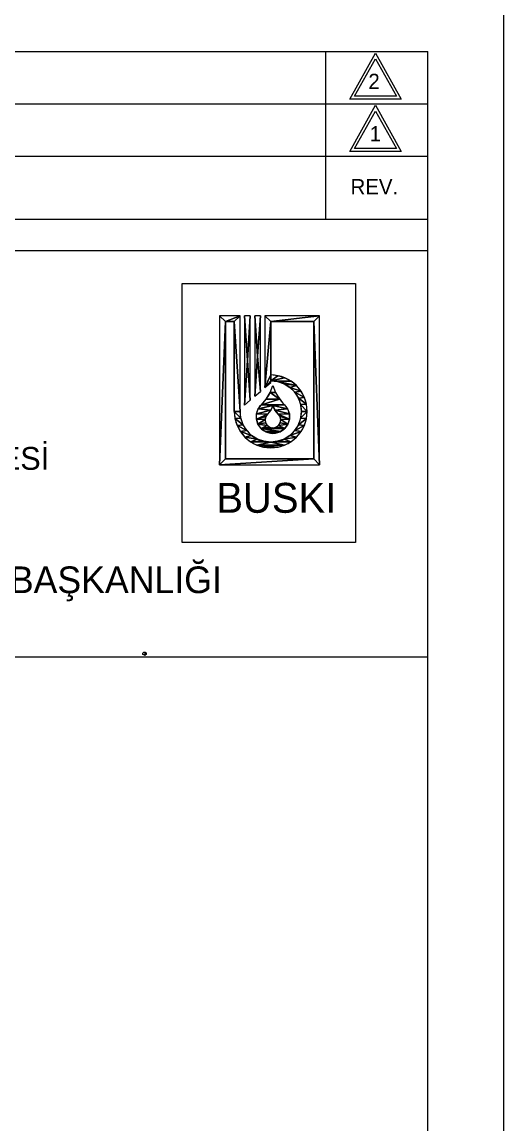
# Model space of a CAD drawing. Extents: x -10 to 1145, y -10 to 821.
# Drawn here: x 1081.7 to 1145, y 138.4 to 283.1 of the extents above; entities that cross this region are included whole.
import ezdxf

# ---------------------------------------------------------------- set-up
doc = ezdxf.new("R2010")
doc.units = 0
for name, color, linetype in [('Level 1', 7, 'Continuous'), ('Level 20', 7, 'Continuous'), ('Level 21', 7, 'Continuous'), ('Level 51', 7, 'Continuous'), ('Level 6', 7, 'Continuous'), ('Level 7', 7, 'Continuous'), ('Level 8', 7, 'Continuous')]:
    doc.layers.add(name, color=color, linetype=linetype)

msp = doc.modelspace()

# ---------------------------------------------------------------- linework, layer by layer
at = {"layer": 'Level 1'}
msp.add_lwpolyline([(1097.86, 200.4), (1097.9, 200.4), (1097.99, 200.36), (1098.03, 200.27), (1098.03, 200.1), (1097.94, 200.02), (1097.82, 199.97), (1097.69, 200.02), (1097.6, 200.1), (1097.6, 200.27), (1097.65, 200.36), (1097.73, 200.4), (1097.86, 200.4), (1097.99, 200.27), (1097.99, 200.14), (1097.9, 200.06), (1097.82, 199.97), (1097.9, 200.1), (1097.9, 200.31), (1097.86, 200.4)], dxfattribs=at)
msp.add_lwpolyline([(1097.86, 200.4), (1097.9, 200.4), (1097.99, 200.36), (1098.03, 200.27), (1098.03, 200.1), (1097.94, 200.02), (1097.82, 199.97), (1097.69, 200.02), (1097.6, 200.1), (1097.6, 200.27), (1097.65, 200.36), (1097.73, 200.4), (1097.86, 200.4), (1097.99, 200.27), (1097.99, 200.14), (1097.9, 200.06), (1097.82, 199.97), (1097.9, 200.1), (1097.9, 200.31), (1097.86, 200.4)], dxfattribs=at)
msp.add_lwpolyline([(1097.86, 200.4), (1097.9, 200.4), (1097.99, 200.36), (1098.03, 200.27), (1098.03, 200.1), (1097.94, 200.02), (1097.82, 199.97), (1097.69, 200.02), (1097.6, 200.1), (1097.6, 200.27), (1097.65, 200.36), (1097.73, 200.4), (1097.86, 200.4), (1097.99, 200.27), (1097.99, 200.14), (1097.9, 200.06), (1097.82, 199.97), (1097.9, 200.1), (1097.9, 200.31), (1097.86, 200.4)], dxfattribs=at)
msp.add_lwpolyline([(1097.86, 200.4), (1097.9, 200.4), (1097.99, 200.36), (1098.03, 200.27), (1098.03, 200.1), (1097.94, 200.02), (1097.82, 199.97), (1097.69, 200.02), (1097.6, 200.1), (1097.6, 200.27), (1097.65, 200.36), (1097.73, 200.4), (1097.86, 200.4), (1097.99, 200.27), (1097.99, 200.14), (1097.9, 200.06), (1097.82, 199.97), (1097.9, 200.1), (1097.9, 200.31), (1097.86, 200.4)], dxfattribs=at)
at = {"layer": 'Level 51'}
msp.add_lwpolyline([(-10, -10), (1145, -10), (1145, 821), (-10, 821)], close=True, dxfattribs=at)
at = {"layer": 'Level 6'}
for p, q in [((967.03, 279.24), (1135, 279.24)), ((967.03, 279.24), (1135, 279.24)), ((967.03, 279.24), (1135, 279.24)), ((967.03, 279.24), (1135, 279.24)), ((970.15, 279.24), (1131.87, 279.24)), ((970.15, 279.24), (1131.87, 279.24)), ((970.15, 279.24), (1131.87, 279.24)), ((970.15, 279.24), (1131.87, 279.24)), ((970.15, 279.24), (1131.87, 279.24)), ((970.15, 279.24), (1131.87, 279.24)), ((970.15, 279.24), (1131.87, 279.24)), ((970.15, 279.24), (1131.87, 279.24)), ((1121.62, 257.23), (1121.62, 279.24)), ((1121.62, 257.23), (1121.62, 279.24)), ((1121.62, 257.23), (1121.62, 279.24)), ((1121.62, 257.23), (1121.62, 279.24)), ((1135, 255.72), (1135, 279.24)), ((1135, 255.72), (1135, 279.24)), ((1135, 255.72), (1135, 279.24)), ((1135, 255.72), (1135, 279.24)), ((1135, 255.72), (1135, 279.24)), ((1135, 255.72), (1135, 279.24)), ((1135, 255.72), (1135, 279.24)), ((1135, 255.72), (1135, 279.24)), ((967.03, 272.38), (1135, 272.38)), ((967.03, 272.38), (1135, 272.38)), ((967.03, 272.38), (1135, 272.38)), ((967.03, 272.38), (1135, 272.38)), ((967.03, 265.52), (1135, 265.52)), ((967.03, 265.52), (1135, 265.52)), ((967.03, 265.52), (1135, 265.52)), ((967.03, 265.52), (1135, 265.52)), ((1135, 0), (1135, 262.93)), ((1135, 0), (1135, 262.93)), ((1135, 0), (1135, 262.93)), ((1135, 0), (1135, 262.93)), ((967.03, 257.23), (1135, 257.23)), ((967.03, 257.23), (1135, 257.23)), ((967.03, 257.23), (1135, 257.23)), ((967.03, 257.23), (1135, 257.23)), ((967.03, 253.14), (1135, 253.14)), ((967.03, 253.14), (1135, 253.14)), ((967.03, 253.14), (1135, 253.14)), ((967.03, 253.14), (1135, 253.14)), ((967.03, 199.78), (1135, 199.78)), ((967.03, 199.78), (1135, 199.78)), ((967.03, 199.78), (1135, 199.78)), ((967.03, 199.78), (1135, 199.78))]:
    msp.add_line(p, q, dxfattribs=at)
at = {"layer": 'Level 7'}
for points in [[(1124.76, 273), (1128.13, 279.05), (1131.5, 273)], [(1124.76, 273), (1128.13, 279.05), (1131.5, 273)], [(1124.76, 273), (1128.13, 279.05), (1131.5, 273)], [(1124.76, 273), (1128.13, 279.05), (1131.5, 273)], [(1125.38, 273.37), (1128.13, 278.3), (1130.88, 273.37)], [(1125.38, 273.37), (1128.13, 278.3), (1130.88, 273.37)], [(1125.38, 273.37), (1128.13, 278.3), (1130.88, 273.37)], [(1125.38, 273.37), (1128.13, 278.3), (1130.88, 273.37)], [(1124.76, 266.14), (1128.13, 272.19), (1131.5, 266.14)], [(1124.76, 266.14), (1128.13, 272.19), (1131.5, 266.14)], [(1124.76, 266.14), (1128.13, 272.19), (1131.5, 266.14)], [(1124.76, 266.14), (1128.13, 272.19), (1131.5, 266.14)], [(1125.38, 266.51), (1128.13, 271.44), (1130.88, 266.51)], [(1125.38, 266.51), (1128.13, 271.44), (1130.88, 266.51)], [(1125.38, 266.51), (1128.13, 271.44), (1130.88, 266.51)], [(1125.38, 266.51), (1128.13, 271.44), (1130.88, 266.51)]]:
    msp.add_lwpolyline(points, close=True, dxfattribs=at)
at = {"layer": 'Level 8'}
for points in [[(1102.73, 248.8), (1125.52, 248.8), (1125.52, 214.79), (1102.73, 214.79)], [(1107.66, 244.55), (1107.66, 225), (1108.42, 243.79)], [(1108.42, 243.79), (1110.34, 244.55), (1107.66, 244.55)], [(1107.66, 244.55), (1107.66, 225), (1108.42, 243.79)], [(1108.42, 243.79), (1110.34, 244.55), (1107.66, 244.55)], [(1110.34, 244.55), (1108.42, 243.79), (1109.59, 243.79)], [(1110.34, 244.55), (1108.42, 243.79), (1109.59, 243.79)], [(1110.34, 244.55), (1109.59, 243.79), (1110.34, 232)], [(1110.34, 244.55), (1109.59, 243.79), (1110.34, 232)], [(1111.31, 238.68), (1111.69, 244.55), (1110.93, 244.55)], [(1111.31, 238.68), (1110.93, 244.55), (1110.93, 232.82)], [(1111.31, 238.68), (1111.69, 244.55), (1110.93, 244.55)], [(1111.31, 238.68), (1110.93, 244.55), (1110.93, 232.82)], [(1111.31, 238.68), (1111.69, 233.46), (1111.69, 244.55)], [(1111.31, 238.68), (1111.69, 233.46), (1111.69, 244.55)], [(1112.65, 239.27), (1113.03, 244.55), (1112.27, 244.55)], [(1112.65, 239.27), (1112.27, 244.55), (1112.27, 233.99)], [(1112.65, 239.27), (1113.03, 244.55), (1112.27, 244.55)], [(1112.65, 239.27), (1112.27, 244.55), (1112.27, 233.99)], [(1112.65, 239.27), (1113.03, 234.63), (1113.03, 244.55)], [(1112.65, 239.27), (1113.03, 234.63), (1113.03, 244.55)], [(1113.61, 244.55), (1113.61, 235.15), (1114.37, 243.79)], [(1114.37, 243.79), (1120.79, 244.55), (1113.61, 244.55)], [(1113.61, 244.55), (1113.61, 235.15), (1114.37, 243.79)], [(1114.37, 243.79), (1120.79, 244.55), (1113.61, 244.55)], [(1120.79, 244.55), (1114.37, 243.79), (1120.03, 243.79)], [(1120.79, 244.55), (1114.37, 243.79), (1120.03, 243.79)], [(1120.79, 244.55), (1120.03, 243.79), (1120.79, 225)], [(1120.79, 244.55), (1120.03, 243.79), (1120.79, 225)], [(1108.42, 243.79), (1107.66, 225), (1108.42, 225.76)], [(1108.42, 243.79), (1107.66, 225), (1108.42, 225.76)], [(1109.59, 243.79), (1109.59, 232), (1110.34, 232)], [(1109.59, 243.79), (1109.59, 232), (1110.34, 232)], [(1114.37, 243.79), (1113.61, 235.15), (1114.37, 236.79)], [(1114.37, 243.79), (1113.61, 235.15), (1114.37, 236.79)], [(1120.03, 243.79), (1120.03, 225.76), (1120.79, 225)], [(1120.03, 243.79), (1120.03, 225.76), (1120.79, 225)], [(1112.65, 239.27), (1112.27, 233.99), (1113.03, 234.63)], [(1112.65, 239.27), (1112.27, 233.99), (1113.03, 234.63)], [(1111.31, 238.68), (1110.93, 232.82), (1111.69, 233.46)], [(1111.31, 238.68), (1110.93, 232.82), (1111.69, 233.46)], [(1114.37, 236.79), (1113.61, 235.15), (1114.37, 236.03)], [(1114.37, 236.79), (1113.61, 235.15), (1114.37, 236.03)], [(1114.37, 236.03), (1113.61, 235.15), (1114.37, 235.8)], [(1114.37, 236.03), (1113.61, 235.15), (1114.37, 235.8)], [(1114.37, 236.79), (1114.37, 236.03), (1115.3, 236.69)], [(1114.37, 236.79), (1114.37, 236.03), (1115.3, 236.69)], [(1115.3, 236.69), (1114.37, 236.03), (1116.2, 236.42)], [(1115.3, 236.69), (1114.37, 236.03), (1116.2, 236.42)], [(1116.2, 236.42), (1114.37, 236.03), (1117.03, 235.98)], [(1116.2, 236.42), (1114.37, 236.03), (1117.03, 235.98)], [(1114.37, 236.03), (1115.27, 235.93), (1117.03, 235.98)], [(1114.37, 236.03), (1115.27, 235.93), (1117.03, 235.98)], [(1117.03, 235.98), (1115.27, 235.93), (1117.75, 235.38)], [(1117.03, 235.98), (1115.27, 235.93), (1117.75, 235.38)], [(1115.27, 235.93), (1116.12, 235.63), (1117.75, 235.38)], [(1115.27, 235.93), (1116.12, 235.63), (1117.75, 235.38)], [(1114.3, 234.47), (1115.53, 233.62), (1113.79, 233.62)], [(1114.3, 234.47), (1115.53, 233.62), (1113.79, 233.62)], [(1114.66, 235.39), (1115.02, 234.47), (1114.3, 234.47)], [(1114.66, 235.39), (1115.02, 234.47), (1114.3, 234.47)], [(1115.02, 234.47), (1115.53, 233.62), (1114.3, 234.47)], [(1115.02, 234.47), (1115.53, 233.62), (1114.3, 234.47)], [(1116.12, 235.63), (1116.88, 235.15), (1117.75, 235.38)], [(1116.12, 235.63), (1116.88, 235.15), (1117.75, 235.38)], [(1117.75, 235.38), (1116.88, 235.15), (1118.35, 234.66)], [(1117.75, 235.38), (1116.88, 235.15), (1118.35, 234.66)], [(1116.88, 235.15), (1117.52, 234.51), (1118.35, 234.66)], [(1116.88, 235.15), (1117.52, 234.51), (1118.35, 234.66)], [(1118.35, 234.66), (1117.52, 234.51), (1118.79, 233.83)], [(1118.35, 234.66), (1117.52, 234.51), (1118.79, 233.83)], [(1117.52, 234.51), (1118, 233.75), (1118.79, 233.83)], [(1117.52, 234.51), (1118, 233.75), (1118.79, 233.83)], [(1115.53, 233.62), (1116.18, 232.88), (1113.14, 232.88)], [(1113.79, 233.62), (1115.53, 233.62), (1113.14, 232.88)], [(1115.53, 233.62), (1116.18, 232.88), (1113.14, 232.88)], [(1113.79, 233.62), (1115.53, 233.62), (1113.14, 232.88)], [(1118.79, 233.83), (1118, 233.75), (1119.06, 232.94)], [(1118.79, 233.83), (1118, 233.75), (1119.06, 232.94)], [(1118, 233.75), (1118.3, 232.9), (1119.06, 232.94)], [(1118, 233.75), (1118.3, 232.9), (1119.06, 232.94)], [(1119.06, 232.94), (1118.3, 232.9), (1119.15, 232)], [(1119.06, 232.94), (1118.3, 232.9), (1119.15, 232)], [(1109.59, 232), (1109.68, 231.07), (1110.44, 231.11)], [(1110.34, 232), (1109.59, 232), (1110.44, 231.11)], [(1109.59, 232), (1109.68, 231.07), (1110.44, 231.11)], [(1110.34, 232), (1109.59, 232), (1110.44, 231.11)], [(1112.51, 231.67), (1113.96, 231.65), (1112.5, 230.98)], [(1112.51, 231.67), (1113.96, 231.65), (1112.5, 230.98)], [(1113.96, 231.65), (1113.72, 231.32), (1112.5, 230.98)], [(1113.96, 231.65), (1113.72, 231.32), (1112.5, 230.98)], [(1112.73, 232.33), (1114.39, 232.16), (1112.51, 231.67)], [(1112.73, 232.33), (1114.39, 232.16), (1112.51, 231.67)], [(1114.39, 232.16), (1113.96, 231.65), (1112.51, 231.67)], [(1114.39, 232.16), (1113.96, 231.65), (1112.51, 231.67)], [(1113.14, 232.88), (1114.66, 232.76), (1112.73, 232.33)], [(1113.14, 232.88), (1114.66, 232.76), (1112.73, 232.33)], [(1114.66, 232.76), (1114.39, 232.16), (1112.73, 232.33)], [(1114.66, 232.76), (1114.39, 232.16), (1112.73, 232.33)], [(1116.18, 232.88), (1114.66, 232.76), (1113.14, 232.88)], [(1116.18, 232.88), (1114.66, 232.76), (1113.14, 232.88)], [(1116.18, 232.88), (1116.59, 232.33), (1114.66, 232.76)], [(1116.18, 232.88), (1116.59, 232.33), (1114.66, 232.76)], [(1114.66, 232.76), (1116.59, 232.33), (1114.93, 232.16)], [(1114.66, 232.76), (1116.59, 232.33), (1114.93, 232.16)], [(1116.59, 232.33), (1116.82, 231.67), (1114.93, 232.16)], [(1116.59, 232.33), (1116.82, 231.67), (1114.93, 232.16)], [(1114.93, 232.16), (1116.82, 231.67), (1115.36, 231.65)], [(1114.93, 232.16), (1116.82, 231.67), (1115.36, 231.65)], [(1116.82, 231.67), (1116.82, 230.98), (1115.36, 231.65)], [(1116.82, 231.67), (1116.82, 230.98), (1115.36, 231.65)], [(1115.36, 231.65), (1116.82, 230.98), (1115.6, 231.32)], [(1115.36, 231.65), (1116.82, 230.98), (1115.6, 231.32)], [(1118.3, 232.9), (1118.4, 232), (1119.15, 232)], [(1118.3, 232.9), (1118.4, 232), (1119.15, 232)], [(1119.15, 232), (1118.3, 231.11), (1119.06, 231.07)], [(1118.4, 232), (1118.3, 231.11), (1119.15, 232)], [(1119.15, 232), (1118.3, 231.11), (1119.06, 231.07)], [(1118.4, 232), (1118.3, 231.11), (1119.15, 232)], [(1110.44, 231.11), (1109.68, 231.07), (1110.74, 230.25)], [(1110.44, 231.11), (1109.68, 231.07), (1110.74, 230.25)], [(1109.68, 231.07), (1109.95, 230.17), (1110.74, 230.25)], [(1109.68, 231.07), (1109.95, 230.17), (1110.74, 230.25)], [(1110.74, 230.25), (1109.95, 230.17), (1111.22, 229.49)], [(1110.74, 230.25), (1109.95, 230.17), (1111.22, 229.49)], [(1109.95, 230.17), (1110.39, 229.34), (1111.22, 229.49)], [(1109.95, 230.17), (1110.39, 229.34), (1111.22, 229.49)], [(1113.72, 231.32), (1113.63, 230.92), (1112.5, 230.98)], [(1113.72, 231.32), (1113.63, 230.92), (1112.5, 230.98)], [(1112.5, 230.98), (1113.63, 230.92), (1112.7, 230.33)], [(1112.5, 230.98), (1113.63, 230.92), (1112.7, 230.33)], [(1113.63, 230.92), (1113.7, 230.52), (1112.7, 230.33)], [(1113.63, 230.92), (1113.7, 230.52), (1112.7, 230.33)], [(1113.7, 230.52), (1113.92, 230.17), (1112.7, 230.33)], [(1113.7, 230.52), (1113.92, 230.17), (1112.7, 230.33)], [(1112.7, 230.33), (1113.92, 230.17), (1113.11, 229.76)], [(1112.7, 230.33), (1113.92, 230.17), (1113.11, 229.76)], [(1113.92, 230.17), (1114.26, 229.94), (1113.11, 229.76)], [(1113.92, 230.17), (1114.26, 229.94), (1113.11, 229.76)], [(1115.4, 230.17), (1116.22, 229.76), (1115.06, 229.94)], [(1115.4, 230.17), (1116.22, 229.76), (1115.06, 229.94)], [(1115.62, 230.52), (1116.62, 230.33), (1115.4, 230.17)], [(1115.62, 230.52), (1116.62, 230.33), (1115.4, 230.17)], [(1116.62, 230.33), (1116.22, 229.76), (1115.4, 230.17)], [(1116.62, 230.33), (1116.22, 229.76), (1115.4, 230.17)], [(1115.6, 231.32), (1116.82, 230.98), (1115.69, 230.92)], [(1115.6, 231.32), (1116.82, 230.98), (1115.69, 230.92)], [(1115.69, 230.92), (1116.62, 230.33), (1115.62, 230.52)], [(1115.69, 230.92), (1116.62, 230.33), (1115.62, 230.52)], [(1116.82, 230.98), (1116.62, 230.33), (1115.69, 230.92)], [(1116.82, 230.98), (1116.62, 230.33), (1115.69, 230.92)], [(1118, 230.25), (1117.52, 229.49), (1118.79, 230.17)], [(1118, 230.25), (1117.52, 229.49), (1118.79, 230.17)], [(1118.79, 230.17), (1117.52, 229.49), (1118.35, 229.34)], [(1118.79, 230.17), (1117.52, 229.49), (1118.35, 229.34)], [(1118.3, 231.11), (1118, 230.25), (1119.06, 231.07)], [(1118.3, 231.11), (1118, 230.25), (1119.06, 231.07)], [(1119.06, 231.07), (1118, 230.25), (1118.79, 230.17)], [(1119.06, 231.07), (1118, 230.25), (1118.79, 230.17)], [(1111.22, 229.49), (1110.39, 229.34), (1111.86, 228.85)], [(1111.22, 229.49), (1110.39, 229.34), (1111.86, 228.85)], [(1110.39, 229.34), (1110.99, 228.62), (1111.86, 228.85)], [(1110.39, 229.34), (1110.99, 228.62), (1111.86, 228.85)], [(1111.86, 228.85), (1110.99, 228.62), (1112.62, 228.37)], [(1111.86, 228.85), (1110.99, 228.62), (1112.62, 228.37)], [(1110.99, 228.62), (1111.71, 228.02), (1112.62, 228.37)], [(1110.99, 228.62), (1111.71, 228.02), (1112.62, 228.37)], [(1114.26, 229.94), (1114.66, 229.86), (1113.11, 229.76)], [(1114.26, 229.94), (1114.66, 229.86), (1113.11, 229.76)], [(1114.66, 229.86), (1116.22, 229.76), (1113.11, 229.76)], [(1114.66, 229.86), (1116.22, 229.76), (1113.11, 229.76)], [(1113.11, 229.76), (1115.66, 229.36), (1113.66, 229.36)], [(1116.22, 229.76), (1115.66, 229.36), (1113.11, 229.76)], [(1113.11, 229.76), (1115.66, 229.36), (1113.66, 229.36)], [(1116.22, 229.76), (1115.66, 229.36), (1113.11, 229.76)], [(1113.66, 229.36), (1115.01, 229.14), (1114.32, 229.14)], [(1115.66, 229.36), (1115.01, 229.14), (1113.66, 229.36)], [(1113.66, 229.36), (1115.01, 229.14), (1114.32, 229.14)], [(1115.66, 229.36), (1115.01, 229.14), (1113.66, 229.36)], [(1115.06, 229.94), (1116.22, 229.76), (1114.66, 229.86)], [(1115.06, 229.94), (1116.22, 229.76), (1114.66, 229.86)], [(1116.88, 228.85), (1116.12, 228.37), (1117.75, 228.62)], [(1116.88, 228.85), (1116.12, 228.37), (1117.75, 228.62)], [(1117.75, 228.62), (1116.12, 228.37), (1117.03, 228.02)], [(1117.75, 228.62), (1116.12, 228.37), (1117.03, 228.02)], [(1117.52, 229.49), (1116.88, 228.85), (1118.35, 229.34)], [(1117.52, 229.49), (1116.88, 228.85), (1118.35, 229.34)], [(1118.35, 229.34), (1116.88, 228.85), (1117.75, 228.62)], [(1118.35, 229.34), (1116.88, 228.85), (1117.75, 228.62)], [(1112.62, 228.37), (1111.71, 228.02), (1113.47, 228.08)], [(1112.62, 228.37), (1111.71, 228.02), (1113.47, 228.08)], [(1113.47, 228.08), (1111.71, 228.02), (1114.37, 227.98)], [(1113.47, 228.08), (1111.71, 228.02), (1114.37, 227.98)], [(1111.71, 228.02), (1112.54, 227.58), (1114.37, 227.98)], [(1111.71, 228.02), (1112.54, 227.58), (1114.37, 227.98)], [(1114.37, 227.98), (1112.54, 227.58), (1116.2, 227.58)], [(1114.37, 227.98), (1112.54, 227.58), (1116.2, 227.58)], [(1112.54, 227.58), (1113.44, 227.31), (1115.3, 227.31)], [(1116.2, 227.58), (1112.54, 227.58), (1115.3, 227.31)], [(1112.54, 227.58), (1113.44, 227.31), (1115.3, 227.31)], [(1116.2, 227.58), (1112.54, 227.58), (1115.3, 227.31)], [(1115.3, 227.31), (1113.44, 227.31), (1114.37, 227.22)], [(1115.3, 227.31), (1113.44, 227.31), (1114.37, 227.22)], [(1115.27, 228.08), (1114.37, 227.98), (1117.03, 228.02)], [(1115.27, 228.08), (1114.37, 227.98), (1117.03, 228.02)], [(1117.03, 228.02), (1114.37, 227.98), (1116.2, 227.58)], [(1117.03, 228.02), (1114.37, 227.98), (1116.2, 227.58)], [(1116.12, 228.37), (1115.27, 228.08), (1117.03, 228.02)], [(1116.12, 228.37), (1115.27, 228.08), (1117.03, 228.02)], [(1120.03, 225.76), (1107.66, 225), (1120.79, 225)], [(1107.66, 225), (1120.03, 225.76), (1108.42, 225.76)], [(1120.03, 225.76), (1107.66, 225), (1120.79, 225)], [(1107.66, 225), (1120.03, 225.76), (1108.42, 225.76)]]:
    msp.add_lwpolyline(points, close=True, dxfattribs=at)
for points in [[(1110.34, 232), (1110.34, 232), (1110.34, 244.55), (1107.66, 244.55), (1107.66, 225), (1120.79, 225), (1120.79, 244.55), (1113.61, 244.55), (1113.61, 235.15), (1114.37, 235.8), (1114.37, 236.03)], [(1110.34, 232), (1110.34, 232), (1110.34, 244.55), (1107.66, 244.55), (1107.66, 225), (1120.79, 225), (1120.79, 244.55), (1113.61, 244.55), (1113.61, 235.15), (1114.37, 235.8), (1114.37, 236.03)], [(1111.69, 244.55), (1110.93, 244.55), (1110.93, 232.82), (1111.69, 233.46), (1111.69, 244.55)], [(1111.69, 244.55), (1110.93, 244.55), (1110.93, 232.82), (1111.69, 233.46), (1111.69, 244.55)], [(1112.27, 233.99), (1113.03, 234.63), (1113.03, 244.55), (1112.27, 244.55), (1112.27, 233.99)], [(1112.27, 233.99), (1113.03, 234.63), (1113.03, 244.55), (1112.27, 244.55), (1112.27, 233.99)], [(1109.59, 232), (1109.59, 232), (1109.59, 243.79), (1108.42, 243.79), (1108.42, 225.76), (1120.03, 225.76), (1120.03, 243.79), (1114.37, 243.79), (1114.37, 236.79)], [(1109.59, 232), (1109.59, 232), (1109.59, 243.79), (1108.42, 243.79), (1108.42, 225.76), (1120.03, 225.76), (1120.03, 243.79), (1114.37, 243.79), (1114.37, 236.79)], [(1114.37, 236.79), (1114.37, 236.78)], [(1114.37, 236.79), (1114.37, 236.78)], [(1114.37, 236.03), (1114.37, 236.03)], [(1114.37, 236.03), (1114.37, 236.03)]]:
    msp.add_lwpolyline(points, dxfattribs=at)
for centre, radius, start, end in [((1114.37, 232), 4.78, 180, 90), ((1114.37, 232), 4.78, 180, 90), ((1114.37, 232), 4.03, 180, 90), ((1114.37, 232), 4.03, 180, 90), ((1109.07, 237.05), 5.83, 314.2894, 343.392), ((1109.07, 237.05), 5.83, 314.2894, 343.392), ((1120.25, 237.05), 5.83, 196.608, 225.7106), ((1120.25, 237.05), 5.83, 196.608, 225.7106), ((1114.66, 231.3), 2.19, 133.9191, 46.0809), ((1114.66, 231.3), 2.19, 133.9191, 46.0809), ((1114.66, 230.89), 1.03, 132.7094, 47.2906), ((1114.66, 230.89), 1.03, 132.7094, 47.2906), ((1112.42, 233.4), 2.33, 311.4103, 344.0384), ((1112.42, 233.4), 2.33, 311.4103, 344.0384), ((1116.91, 233.4), 2.33, 195.9616, 228.5897), ((1116.91, 233.4), 2.33, 195.9616, 228.5897)]:
    msp.add_arc(centre, radius, start, end, dxfattribs=at)

# ---------------------------------------------------------------- texts
at = {"layer": 'Level 1'}
for s, p in [('2', (1127.2, 274.33)), ('1', (1127.37, 267.46))]:
    msp.add_text(s, height=2, dxfattribs=at).set_placement(p)
at = {"layer": 'Level 20'}
msp.add_text('PLANLAMA YATIRIM VE İNŞAAT DAİRE BAŞKANLIĞI', height=3.5, dxfattribs=at).set_placement((992.21, 208.14))
at = {"layer": 'Level 21'}
msp.add_text('BUSKI', height=3.926, dxfattribs=at).set_placement((1107.23, 218.69))
msp.add_text('BUSKI', height=3.926, dxfattribs=at).set_placement((1107.23, 218.69))
at = {"layer": 'Level 7'}
for s, height, p in [('REV.', 2, (1124.86, 260.5)), ('BURSA SU VE KANALİZASYON İDARESİ', 3, (1009.26, 224.33))]:
    msp.add_text(s, height=height, dxfattribs=at).set_placement(p)

doc.saveas('drawing.dxf')
